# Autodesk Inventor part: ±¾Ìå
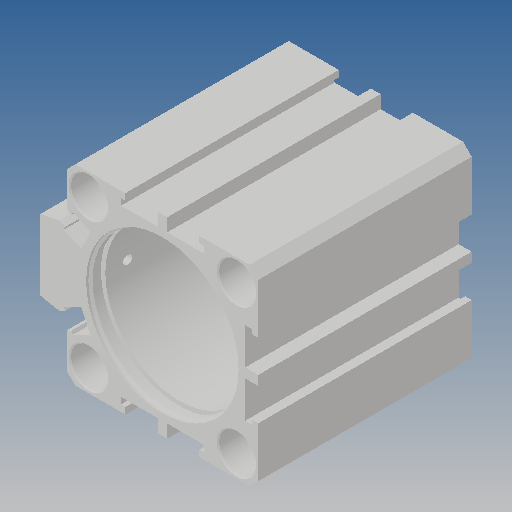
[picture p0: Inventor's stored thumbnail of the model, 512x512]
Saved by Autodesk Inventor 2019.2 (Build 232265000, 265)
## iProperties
Created: 2013-07
Part Number: ±¾Ìå
Material: Ogólny
Document SubType Name: Modeling
Designer: CADENGINEERING4
Density: 1 g/cm^3
Appearance: Domyślna
Author: CADENGINEERING4
Revision Number: ÈÎºÎ
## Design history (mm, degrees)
feature "¾µÏò1"
node "Bryła1"
